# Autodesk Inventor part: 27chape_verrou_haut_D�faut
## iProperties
Created: 2011-01
Part Number: 27chape_verrou_haut_D�faut
Document SubType Name: Modeling
Designer: eric
Density: 1 g/cm^3
Mass: 9.58977 g
Surface Area: 105.012 cm^2
Volume: 9.58977 cm^3
Author: eric
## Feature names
1. Base1
